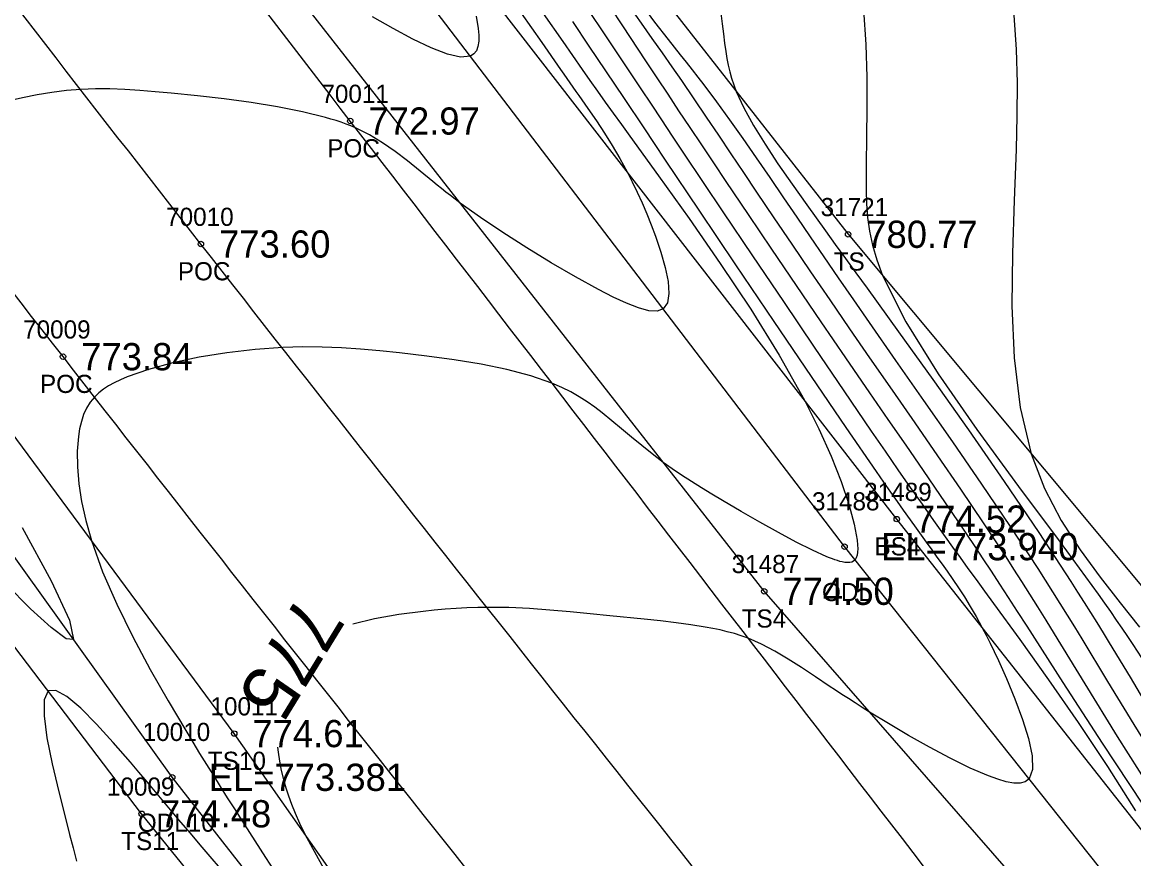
# Model space of a CAD drawing. Extents: x 1376587 to 1378239, y 1000335 to 1003031.
# Drawn here: x 1378121.7 to 1378182.9, y 1000400.9 to 1000447 of the extents above; entities that cross this region are included whole.
import ezdxf

# ---------------------------------------------------------------- set-up
doc = ezdxf.new("R2010")
doc.units = 0
for name, color, linetype in [('RD_DTM_BkLn1', 7, 'Continuous'), ('RD_DTM_BkLn2', 7, 'Continuous'), ('RD_DTM_BkLn_txCode', 7, 'Continuous'), ('RD_DTM_Major1', 7, 'Continuous'), ('RD_DTM_Major1_Lbl', 7, 'Continuous'), ('RD_DTM_Minor1', 7, 'Continuous'), ('RD_EX_H2O', 7, 'Continuous'), ('RD_EX_H2O_txCode', 7, 'Continuous'), ('RD_EX_Road', 7, 'Continuous'), ('RD_EX_Road_txCode', 7, 'Continuous'), ('RD_EX_TX_H2O_ELEV', 7, 'Continuous'), ('RD_EX_TX_Misc_ELEV', 7, 'Continuous'), ('RD_EX_TX_Road_ELEV', 7, 'Continuous'), ('RD_HC_Survey_ELEV', 7, 'Continuous'), ('RD_HC_Survey_txCode', 7, 'Continuous'), ('RD_SMD_Locator', 7, 'Continuous')]:
    doc.layers.add(name, color=color, linetype=linetype)

msp = doc.modelspace()

# ---------------------------------------------------------------- linework, layer by layer
at = {"layer": 'RD_DTM_BkLn1'}
msp.add_spline([(1378169.212, 1000387.103), (1378131.506, 1000434.744), (1378095.477, 1000481.988), (1378063.033, 1000526.867), (1378030.177, 1000574.233), (1377998.011, 1000622.539), (1377965.721, 1000673.201), (1377936, 1000721.493), (1377904.113, 1000773.429), (1377890.868, 1000795.129)], degree=3, dxfattribs=at)
at = {"layer": 'RD_DTM_BkLn2'}
for points in [[(1378190.398, 1000393.443), (1378169.827, 1000419.586), (1378140.073, 1000457.945), (1378106.638, 1000503.045), (1378080.309, 1000536.837), (1378054.858, 1000574.217), (1378031.288, 1000609.189), (1378023.609, 1000623.494), (1378023.602, 1000635.418), (1378048.247, 1000654.107), (1378063.88, 1000653.985)], [(1378152.795, 1000376.442), (1378153.623, 1000378.891), (1378133.341, 1000407.77), (1378106.208, 1000444.47), (1378079.422, 1000481.908), (1378052.603, 1000518.078), (1378027.38, 1000556.138), (1377999.887, 1000593.901), (1377975.443, 1000634.683), (1377966.188, 1000647.973)], [(1378152.458, 1000376.254), (1378150.255, 1000376.168), (1378128.245, 1000403.35), (1378101.014, 1000439.163), (1378072.773, 1000477.242), (1378039.24, 1000510.344), (1378015.855, 1000547.194), (1377989.301, 1000588.148), (1377962.727, 1000626.954), (1377952.76, 1000642.197)], [(1378184.932, 1000389.914), (1378162.528, 1000415.61), (1378132.296, 1000454.253), (1378102.474, 1000500.023), (1378076.88, 1000534.536), (1378051.356, 1000571.753), (1378025.282, 1000608.511), (1378019.607, 1000621.768)], [(1378038.697, 1000617.909), (1378063.36, 1000579.778), (1378090.166, 1000542.645), (1378113.6, 1000508.056), (1378141.542, 1000468.001), (1378167.145, 1000435.28), (1378192.427, 1000404.958)]]:
    msp.add_lwpolyline(points, dxfattribs=at)
at = {"layer": 'RD_DTM_Major1'}
for points in [[(1378160.145, 1000447.465), (1378160.212, 1000446.868), (1378160.277, 1000446.322), (1378160.343, 1000445.819), (1378160.41, 1000445.353), (1378160.475, 1000444.963), (1378160.548, 1000444.591), (1378160.632, 1000444.231), (1378160.731, 1000443.874), (1378160.849, 1000443.516), (1378160.989, 1000443.148), (1378161.405, 1000442.248), (1378161.94, 1000441.276), (1378162.574, 1000440.243), (1378163.286, 1000439.162), (1378164.058, 1000438.045), (1378164.868, 1000436.902), (1378165.381, 1000436.188), (1378165.904, 1000435.463), (1378166.442, 1000434.719), (1378167, 1000433.951), (1378167.581, 1000433.151), (1378168.189, 1000432.313), (1378169.925, 1000429.907), (1378171.807, 1000427.274), (1378173.767, 1000424.498), (1378175.734, 1000421.661), (1378177.641, 1000418.848), (1378179.419, 1000416.142), (1378179.787, 1000415.567), (1378180.146, 1000415), (1378180.499, 1000414.44), (1378180.845, 1000413.883), (1378181.186, 1000413.329), (1378181.524, 1000412.777), (1378182.671, 1000410.872), (1378183.788, 1000409.004)], [(1378151.964, 1000447.006), (1378152.872, 1000445.65), (1378153.781, 1000444.293), (1378154.807, 1000442.759), (1378155.89, 1000441.14), (1378156.468, 1000440.277), (1378157.078, 1000439.366), (1378158.926, 1000436.61), (1378160.954, 1000433.594), (1378163.054, 1000430.482), (1378165.115, 1000427.438), (1378167.03, 1000424.628), (1378168.69, 1000422.215), (1378169.101, 1000421.623), (1378169.485, 1000421.073), (1378169.844, 1000420.562), (1378170.181, 1000420.086), (1378170.794, 1000419.225), (1378171.449, 1000418.316), (1378171.751, 1000417.899), (1378172.04, 1000417.499), (1378172.32, 1000417.108), (1378172.595, 1000416.72), (1378172.913, 1000416.263), (1378173.23, 1000415.793), (1378173.548, 1000415.301), (1378173.871, 1000414.778), (1378174.198, 1000414.216), (1378174.534, 1000413.604), (1378174.752, 1000413.185), (1378174.974, 1000412.745), (1378175.198, 1000412.284), (1378175.423, 1000411.804), (1378175.648, 1000411.308), (1378175.873, 1000410.796), (1378176.336, 1000409.675), (1378176.751, 1000408.552), (1378177.077, 1000407.491), (1378177.273, 1000406.551), (1378177.298, 1000405.793), (1378177.112, 1000405.279), (1378176.901, 1000405.116), (1378176.616, 1000405.041), (1378176.265, 1000405.044), (1378175.853, 1000405.118), (1378175.388, 1000405.252), (1378174.876, 1000405.437), (1378173.866, 1000405.871), (1378172.768, 1000406.408), (1378171.625, 1000407.017), (1378170.476, 1000407.666), (1378169.363, 1000408.324), (1378168.327, 1000408.958), (1378167.922, 1000409.212), (1378167.535, 1000409.458), (1378167.163, 1000409.697), (1378166.803, 1000409.931), (1378166.453, 1000410.162), (1378166.108, 1000410.391), (1378165.342, 1000410.904), (1378164.589, 1000411.403), (1378163.846, 1000411.877), (1378163.11, 1000412.312), (1378162.378, 1000412.697), (1378161.647, 1000413.018), (1378161.266, 1000413.157), (1378160.882, 1000413.278), (1378160.493, 1000413.384), (1378160.097, 1000413.477), (1378159.692, 1000413.561), (1378159.276, 1000413.636), (1378158.495, 1000413.76), (1378157.673, 1000413.871), (1378156.814, 1000413.973), (1378155.918, 1000414.07), (1378154.031, 1000414.262), (1378152.951, 1000414.372), (1378151.847, 1000414.479), (1378150.726, 1000414.576), (1378149.597, 1000414.655), (1378148.469, 1000414.708), (1378147.35, 1000414.725), (1378146.753, 1000414.718), (1378146.159, 1000414.698), (1378145.563, 1000414.667), (1378144.963, 1000414.624), (1378144.357, 1000414.569), (1378143.741, 1000414.502), (1378142.409, 1000414.324), (1378141.075, 1000414.083), (1378139.878, 1000413.79)], [(1378135.73, 1000407.017), (1378135.756, 1000406.75), (1378135.828, 1000406.249), (1378135.93, 1000405.727), (1378136.066, 1000405.174), (1378136.183, 1000404.773), (1378136.324, 1000404.346), (1378136.495, 1000403.884), (1378136.7, 1000403.382), (1378136.946, 1000402.831), (1378137.237, 1000402.223), (1378139.096, 1000398.804)]]:
    msp.add_lwpolyline(points, dxfattribs=at)
at = {"layer": 'RD_DTM_Minor1'}
for points in [[(1378154.038, 1000447.794), (1378154.717, 1000446.764), (1378155.994, 1000444.832), (1378156.609, 1000443.904), (1378157.211, 1000442.997), (1378157.816, 1000442.086), (1378158.432, 1000441.16), (1378159.066, 1000440.207), (1378159.727, 1000439.218), (1378160.421, 1000438.181), (1378161.636, 1000436.374), (1378162.932, 1000434.454), (1378164.28, 1000432.467), (1378165.648, 1000430.456), (1378167.007, 1000428.467), (1378168.328, 1000426.544), (1378169.341, 1000425.077), (1378170.32, 1000423.659), (1378171.277, 1000422.271), (1378172.222, 1000420.891), (1378173.166, 1000419.5), (1378174.119, 1000418.075), (1378174.564, 1000417.403), (1378175.016, 1000416.714), (1378175.481, 1000416.003), (1378175.961, 1000415.264), (1378176.46, 1000414.492), (1378176.982, 1000413.681), (1378178.966, 1000410.59), (1378181.137, 1000407.234), (1378183.363, 1000403.874)], [(1378155.119, 1000447.786), (1378155.746, 1000446.905), (1378156.338, 1000446.07), (1378156.901, 1000445.272), (1378157.441, 1000444.502), (1378157.964, 1000443.749), (1378158.655, 1000442.743), (1378159.335, 1000441.742), (1378160.012, 1000440.738), (1378160.695, 1000439.72), (1378161.391, 1000438.679), (1378162.11, 1000437.605), (1378163.056, 1000436.196), (1378164.046, 1000434.73), (1378165.073, 1000433.215), (1378166.132, 1000431.662), (1378167.217, 1000430.08), (1378168.324, 1000428.478), (1378169.565, 1000426.693), (1378170.818, 1000424.894), (1378172.077, 1000423.077), (1378173.336, 1000421.241), (1378174.587, 1000419.384), (1378175.824, 1000417.503), (1378176.259, 1000416.828), (1378176.694, 1000416.147), (1378177.132, 1000415.454), (1378177.576, 1000414.747), (1378178.027, 1000414.02), (1378178.49, 1000413.27), (1378180.181, 1000410.507), (1378181.969, 1000407.604), (1378183.786, 1000404.743)], [(1378155.726, 1000447.998), (1378156.488, 1000446.966), (1378157.24, 1000446.006), (1378157.575, 1000445.587), (1378157.904, 1000445.173), (1378158.231, 1000444.762), (1378158.555, 1000444.351), (1378158.879, 1000443.937), (1378159.203, 1000443.515), (1378159.908, 1000442.571), (1378160.624, 1000441.584), (1378161.349, 1000440.558), (1378162.086, 1000439.496), (1378162.835, 1000438.404), (1378163.598, 1000437.285), (1378164.317, 1000436.228), (1378165.054, 1000435.146), (1378165.816, 1000434.031), (1378166.607, 1000432.876), (1378167.435, 1000431.673), (1378168.305, 1000430.417), (1378169.761, 1000428.33), (1378171.301, 1000426.128), (1378172.889, 1000423.846), (1378174.49, 1000421.518), (1378176.069, 1000419.178), (1378177.59, 1000416.862), (1378178.001, 1000416.221), (1378178.408, 1000415.582), (1378178.811, 1000414.942), (1378179.212, 1000414.298), (1378179.613, 1000413.649), (1378180.017, 1000412.99), (1378181.435, 1000410.647), (1378182.874, 1000408.269), (1378184.309, 1000405.958)], [(1378149.149, 1000447.472), (1378150.274, 1000445.844), (1378151.308, 1000444.359), (1378151.486, 1000444.106), (1378151.829, 1000443.617), (1378152.159, 1000443.148), (1378152.319, 1000442.92), (1378152.814, 1000442.212), (1378153.283, 1000441.527), (1378153.731, 1000440.85), (1378154.16, 1000440.168), (1378154.575, 1000439.465), (1378154.979, 1000438.728), (1378155.261, 1000438.175), (1378155.537, 1000437.601), (1378155.805, 1000437.011), (1378156.062, 1000436.408), (1378156.307, 1000435.796), (1378156.538, 1000435.179), (1378156.835, 1000434.298), (1378157.075, 1000433.452), (1378157.232, 1000432.679), (1378157.282, 1000432.016), (1378157.203, 1000431.499), (1378156.968, 1000431.165), (1378156.628, 1000431.045), (1378156.168, 1000431.071), (1378155.602, 1000431.222), (1378154.944, 1000431.48), (1378154.209, 1000431.825), (1378153.41, 1000432.238), (1378152.138, 1000432.938), (1378150.804, 1000433.714), (1378149.454, 1000434.537), (1378148.137, 1000435.379), (1378146.901, 1000436.211), (1378145.791, 1000437.003), (1378145.516, 1000437.209), (1378145.252, 1000437.411), (1378144.998, 1000437.609), (1378144.753, 1000437.803), (1378144.514, 1000437.994), (1378144.282, 1000438.183), (1378143.573, 1000438.764), (1378142.887, 1000439.32), (1378142.207, 1000439.843), (1378141.515, 1000440.325), (1378140.793, 1000440.761), (1378140.025, 1000441.141), (1378139.768, 1000441.25), (1378139.504, 1000441.353), (1378139.233, 1000441.45), (1378138.955, 1000441.543), (1378138.668, 1000441.632), (1378138.372, 1000441.718), (1378137.103, 1000442.031), (1378135.727, 1000442.302), (1378134.279, 1000442.535), (1378132.795, 1000442.735), (1378131.314, 1000442.907), (1378129.87, 1000443.055), (1378128.994, 1000443.138), (1378128.144, 1000443.208), (1378127.314, 1000443.261), (1378126.5, 1000443.291), (1378125.699, 1000443.294), (1378124.905, 1000443.265), (1378124.098, 1000443.197), (1378123.293, 1000443.095), (1378122.489, 1000442.961), (1378121.685, 1000442.801), (1378120.879, 1000442.617)], [(1378150.362, 1000447.45), (1378151.432, 1000445.895), (1378152.51, 1000444.352), (1378152.928, 1000443.761), (1378153.349, 1000443.168), (1378153.776, 1000442.568), (1378154.213, 1000441.959), (1378154.661, 1000441.336), (1378155.124, 1000440.695), (1378156.706, 1000438.508), (1378158.391, 1000436.151), (1378160.108, 1000433.68), (1378161.788, 1000431.149), (1378163.358, 1000428.616), (1378164.747, 1000426.135), (1378165.534, 1000424.555), (1378166.206, 1000423.053), (1378166.759, 1000421.658), (1378167.186, 1000420.401), (1378167.485, 1000419.312), (1378167.648, 1000418.422), (1378167.672, 1000418.174), (1378167.679, 1000417.953), (1378167.669, 1000417.758), (1378167.641, 1000417.592), (1378167.594, 1000417.454), (1378167.527, 1000417.345), (1378167.448, 1000417.272), (1378167.353, 1000417.223), (1378167.241, 1000417.196), (1378167.113, 1000417.189), (1378166.97, 1000417.201), (1378166.811, 1000417.23), (1378166.689, 1000417.26), (1378166.56, 1000417.298), (1378166.424, 1000417.343), (1378166.281, 1000417.395), (1378166.131, 1000417.453), (1378165.973, 1000417.517), (1378165.182, 1000417.873), (1378164.282, 1000418.323), (1378163.307, 1000418.844), (1378162.287, 1000419.414), (1378161.253, 1000420.009), (1378160.239, 1000420.608), (1378159.645, 1000420.965), (1378159.07, 1000421.317), (1378158.515, 1000421.666), (1378157.98, 1000422.013), (1378157.465, 1000422.361), (1378156.971, 1000422.712), (1378156.36, 1000423.175), (1378155.779, 1000423.64), (1378155.219, 1000424.104), (1378154.673, 1000424.562), (1378154.135, 1000425.009), (1378153.596, 1000425.441), (1378153.192, 1000425.748), (1378152.776, 1000426.043), (1378152.34, 1000426.325), (1378151.877, 1000426.592), (1378151.378, 1000426.844), (1378150.836, 1000427.08), (1378149.67, 1000427.481), (1378148.358, 1000427.824), (1378146.939, 1000428.115), (1378145.454, 1000428.361), (1378143.943, 1000428.57), (1378142.444, 1000428.747), (1378141.366, 1000428.859), (1378140.305, 1000428.954), (1378139.251, 1000429.025), (1378138.192, 1000429.067), (1378137.118, 1000429.075), (1378136.017, 1000429.045), (1378134.487, 1000428.937), (1378132.936, 1000428.757), (1378131.41, 1000428.509), (1378129.955, 1000428.199), (1378128.619, 1000427.835), (1378127.447, 1000427.421), (1378127.079, 1000427.263), (1378126.738, 1000427.097), (1378126.426, 1000426.923), (1378126.141, 1000426.738), (1378125.886, 1000426.54), (1378125.661, 1000426.328), (1378125.412, 1000426.029), (1378125.209, 1000425.702), (1378125.048, 1000425.349), (1378124.924, 1000424.969), (1378124.831, 1000424.563), (1378124.764, 1000424.131), (1378124.703, 1000423.335), (1378124.709, 1000422.47), (1378124.784, 1000421.539), (1378124.935, 1000420.549), (1378125.164, 1000419.504), (1378125.475, 1000418.41), (1378126.098, 1000416.686), (1378126.875, 1000414.901), (1378127.762, 1000413.095), (1378128.719, 1000411.308), (1378129.703, 1000409.577), (1378130.671, 1000407.943), (1378131.058, 1000407.303), (1378131.439, 1000406.679), (1378131.816, 1000406.067), (1378132.194, 1000405.46), (1378132.574, 1000404.852), (1378132.961, 1000404.238), (1378133.354, 1000403.618), (1378133.758, 1000402.981), (1378134.176, 1000402.325), (1378135.065, 1000400.941), (1378135.54, 1000400.205)], [(1378146.667, 1000447.297), (1378146.782, 1000446.616), (1378146.813, 1000446.248), (1378146.808, 1000445.918), (1378146.764, 1000445.633), (1378146.676, 1000445.397), (1378146.539, 1000445.217), (1378146.348, 1000445.097), (1378145.808, 1000445.045), (1378145.078, 1000445.209), (1378144.192, 1000445.55), (1378143.186, 1000446.031), (1378142.097, 1000446.612), (1378140.96, 1000447.255)], [(1378152.891, 1000447.554), (1378153.671, 1000446.384), (1378155.735, 1000443.289), (1378156.296, 1000442.447), (1378156.871, 1000441.585), (1378157.466, 1000440.693), (1378158.089, 1000439.759), (1378160.253, 1000436.523), (1378161.885, 1000434.091), (1378163.581, 1000431.57), (1378165.279, 1000429.057), (1378166.913, 1000426.647), (1378168.423, 1000424.435), (1378169.18, 1000423.333), (1378169.891, 1000422.305), (1378170.566, 1000421.335), (1378171.217, 1000420.407), (1378171.854, 1000419.506), (1378172.488, 1000418.617), (1378172.899, 1000418.045), (1378173.317, 1000417.465), (1378173.746, 1000416.871), (1378174.192, 1000416.257), (1378174.656, 1000415.617), (1378175.145, 1000414.944), (1378176.594, 1000412.946), (1378178.175, 1000410.735), (1378179.813, 1000408.379), (1378181.436, 1000405.95), (1378182.969, 1000403.515)], [(1378167.991, 1000447.64), (1378168.129, 1000445.731), (1378168.184, 1000443.93), (1378168.186, 1000442.232), (1378168.16, 1000440.633), (1378168.136, 1000439.128), (1378168.139, 1000437.712), (1378168.164, 1000436.954), (1378168.221, 1000436.206), (1378168.324, 1000435.453), (1378168.486, 1000434.678), (1378168.721, 1000433.867), (1378169.044, 1000433.003), (1378170.322, 1000430.463), (1378172.113, 1000427.59), (1378174.241, 1000424.519), (1378176.533, 1000421.382), (1378178.815, 1000418.312), (1378180.912, 1000415.445), (1378181.256, 1000414.962), (1378181.588, 1000414.489), (1378181.91, 1000414.026), (1378182.223, 1000413.57), (1378182.526, 1000413.122), (1378182.82, 1000412.681), (1378183.778, 1000411.204)], [(1378176.277, 1000447.358), (1378176.395, 1000445.469), (1378176.447, 1000443.633), (1378176.444, 1000441.808), (1378176.401, 1000439.954), (1378176.293, 1000437.14), (1378176.193, 1000434.244), (1378176.167, 1000431.334), (1378176.286, 1000428.477), (1378176.616, 1000425.738), (1378177.228, 1000423.187), (1378177.969, 1000421.277), (1378178.887, 1000419.518), (1378179.932, 1000417.895), (1378181.024, 1000416.38), (1378182.13, 1000414.965), (1378183.184, 1000413.628)], [(1378121.657, 1000419.122), (1378123.254, 1000416.183), (1378124.279, 1000414.014), (1378124.497, 1000412.951), (1378124.081, 1000412.998), (1378123.262, 1000413.606), (1378122.133, 1000414.65), (1378120.789, 1000416.008)], [(1378132.579, 1000400.334), (1378132.011, 1000400.998), (1378131.462, 1000401.645), (1378130.927, 1000402.275), (1378130.405, 1000402.893), (1378129.933, 1000403.455), (1378129.468, 1000404.009), (1378129.007, 1000404.558), (1378128.547, 1000405.103), (1378128.088, 1000405.645), (1378127.626, 1000406.187), (1378126.679, 1000407.277), (1378125.754, 1000408.293), (1378124.891, 1000409.161), (1378124.133, 1000409.806), (1378123.52, 1000410.152), (1378123.093, 1000410.125), (1378122.876, 1000409.638), (1378122.87, 1000408.742), (1378123.031, 1000407.533), (1378123.316, 1000406.105), (1378123.681, 1000404.551), (1378124.083, 1000402.965), (1378124.278, 1000402.21), (1378124.471, 1000401.47), (1378124.66, 1000400.74)]]:
    msp.add_lwpolyline(points, dxfattribs=at)
at = {"layer": 'RD_EX_H2O'}
for points in [[(1378150.92, 1000378.554), (1378129.931, 1000405.361), (1378103.429, 1000442.377), (1378075.971, 1000479.612), (1378048.045, 1000515.879), (1378023.997, 1000553.212), (1377996.392, 1000591.758), (1377970.527, 1000631.657), (1377963.482, 1000646.08)], [(1378187.963, 1000391.619), (1378166.952, 1000418.069), (1378136.831, 1000457.58), (1378104.578, 1000501.856), (1378079.015, 1000536.042), (1378053.898, 1000573.861), (1378029.308, 1000608.167), (1378022.926, 1000618.73)]]:
    msp.add_lwpolyline(points, dxfattribs=at)
at = {"layer": 'RD_EX_Road'}
for points in [[(1378177.15, 1000392.854), (1378139.733, 1000441.521), (1378104.671, 1000487.69), (1378071.786, 1000533.085), (1378038.454, 1000579.804), (1378007.554, 1000627.96), (1377974.27, 1000678.859), (1377944.465, 1000727.117), (1377913.028, 1000778.581), (1377899.668, 1000800.294)], [(1378161.362, 1000381.162), (1378123.914, 1000428.538), (1378087.578, 1000476.324), (1378055.075, 1000520.944), (1378021.673, 1000568.713), (1377989.952, 1000617.081), (1377957.327, 1000668.378), (1377927.534, 1000716.552), (1377895.409, 1000768.824), (1377883.752, 1000788.501)]]:
    msp.add_spline(points, degree=3, dxfattribs=at)
at = {"layer": 'RD_SMD_Locator'}
for centre in [(1378139.733, 1000441.521), (1378167.145, 1000435.28), (1378131.506, 1000434.744), (1378123.914, 1000428.538), (1378169.827, 1000419.586), (1378166.952, 1000418.069), (1378162.528, 1000415.61), (1378133.341, 1000407.77), (1378129.931, 1000405.361), (1378128.245, 1000403.35)]:
    msp.add_circle(centre, 0.15, dxfattribs=at)

# ---------------------------------------------------------------- texts
at = {"layer": 'RD_DTM_BkLn_txCode'}
for s, p in [('31721', (1378165.633, 1000436.28)), ('TS', (1378166.35, 1000433.28)), ('31489', (1378168.032, 1000420.586)), ('BS4', (1378168.599, 1000417.586)), ('31487', (1378160.733, 1000416.61)), ('TS4', (1378161.284, 1000413.61)), ('10011', (1378132.034, 1000408.77)), ('TS10', (1378131.892, 1000405.77)), ('10009', (1378126.332, 1000404.35)), ('TS11', (1378127.119, 1000401.35))]:
    msp.add_text(s, height=1, dxfattribs=at).set_placement(p)
at = {"layer": 'RD_DTM_Major1_Lbl'}
msp.add_text('775', height=3, rotation=238.51522, dxfattribs=at).set_placement((1378136.954, 1000415.538))
at = {"layer": 'RD_EX_H2O_txCode'}
for s, p in [('31488', (1378165.157, 1000420.069)), ('ODL', (1378165.708, 1000415.069)), ('10010', (1378128.301, 1000407.361)), ('ODL10', (1378128.033, 1000402.361))]:
    msp.add_text(s, height=1, dxfattribs=at).set_placement(p)
at = {"layer": 'RD_EX_Road_txCode'}
for s, p in [('70011', (1378138.142, 1000442.521)), ('POC', (1378138.465, 1000439.521)), ('70009', (1378121.717, 1000429.538)), ('POC', (1378122.646, 1000426.538))]:
    msp.add_text(s, height=1, dxfattribs=at).set_placement(p)
at = {"layer": 'RD_EX_TX_H2O_ELEV'}
for s, p in [('EL=773.940', (1378168.952, 1000417.319)), ('EL=773.381', (1378131.931, 1000404.611))]:
    msp.add_text(s, height=1.5, dxfattribs=at).set_placement(p)
at = {"layer": 'RD_EX_TX_Misc_ELEV'}
for s, p in [('780.77', (1378168.145, 1000434.53)), ('774.52', (1378170.827, 1000418.836)), ('774.50', (1378163.528, 1000414.86)), ('774.61', (1378134.341, 1000407.02)), ('774.48', (1378129.245, 1000402.6))]:
    msp.add_text(s, height=1.5, dxfattribs=at).set_placement(p)
at = {"layer": 'RD_EX_TX_Road_ELEV'}
for s, p in [('772.97', (1378140.733, 1000440.771)), ('773.84', (1378124.914, 1000427.788))]:
    msp.add_text(s, height=1.5, dxfattribs=at).set_placement(p)
at = {"layer": 'RD_HC_Survey_ELEV'}
msp.add_text('773.60', height=1.5, dxfattribs=at).set_placement((1378132.506, 1000433.994))
at = {"layer": 'RD_HC_Survey_txCode'}
for s, p in [('70010', (1378129.593, 1000435.744)), ('POC', (1378130.238, 1000432.744))]:
    msp.add_text(s, height=1, dxfattribs=at).set_placement(p)

doc.saveas('drawing.dxf')
